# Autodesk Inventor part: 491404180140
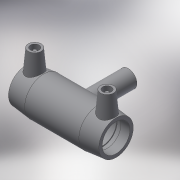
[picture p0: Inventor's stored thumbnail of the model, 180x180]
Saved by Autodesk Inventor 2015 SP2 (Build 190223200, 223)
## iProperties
Created: 2017-06
Part Number: 491404180140
Material: Generic
Description: PLASSON REDUCING TEE 180x140x180
Document SubType Name: Modeling
Designer: KIM
Mass: 57.3761 g
Surface Area: 241.06 cm^2
Volume: 57.3761 cm^3
Density: 1 g/cm^3
Appearance: Default
Author: KIM
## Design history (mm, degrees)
derived "491404.ipt"
feature "Solid1::491404.ipt"
tag "TaggingFeature1"
body "Solid1"
other parameters: "d0" = 422, "d2" = 245, "d3" = 106, "d4" = 84.4, "d5" = 220.5, "d6" = 171, "d8" = 168 deg, "d10" = 42.4, "d11" = 14.13333, "d13" = 422, "d14" = 17.6296, "d17" = 162, "d19" = 3.52592, "d20" = 168 deg, "d22" = 227.85, "d23" = 245, "d25" = 135 deg, "d26" = 295.4, "d29" = 116, "d30" = 15, "d31" = 168.8, "d34" = 5 deg, "d35" = 15, "d39" = 5 deg, "d41" = 4, "d42" = 14, "d43" = 0, "d45" = 4, "d46" = 6, "d47" = 0, "d48" = -237, "d51" = 0, "d52" = 112, "d54" = 0, "d55" = 220.5, "d56" = 245, "d57" = 147.7, "d58" = 135 deg, "d59" = 106, "d60" = 106, "d61" = 135 deg, "d62" = 237, "d72" = 192.01, "d73" = 96.005, "d74" = -237, "d75" = 147, "d77" = 0, "d78" = 112, "d80" = 0, "d82" = 114.5, "d83" = 0, "d84" = 3, "d85" = 0, "d86" = 35.33333, "d87" = 223.293, "d88" = 14.13333, "d89" = 3, "d90" = 0, "L_" = 422, "L_1" = 106, "D_" = 245, "A_" = 116, "d_2" = 12, "H_" = 237
